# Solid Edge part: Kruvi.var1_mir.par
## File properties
Author: jaanm
Template: Ansi Inch Part.par
Last saved by: jaanm
Revision: 2
Application: Solid Edge
Accuracy: 0,990
Username: jaanm
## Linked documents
Kruvi.var1.par
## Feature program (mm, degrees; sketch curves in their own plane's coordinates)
part copy "CopiedPart_1"
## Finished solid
Body 1: solid body, 36 faces, 97 edges, 64 vertices.
  Faces by surface: plane 23, cylinder 10, spline 2, cone 1
  Edges by curve: line 56, circle 33, intersection 4, spline 4
Bounding box of the edges (mm; curved faces can reach further): 20.000 x 58.500 x 20.000, from (-10, -46.5, -10) to (10, 12, 10).
Cylindrical faces by radius (mm): R3.5 x1, R5 x1, R7 x7, R10 x1
Conical faces (half-angle, radius in mm at the cone's reference point): 45 deg R5 x1
Planar faces by outward normal: +y 8, -y 1, -z 1, oblique 13
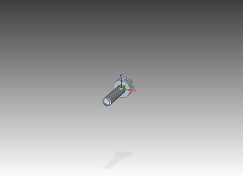
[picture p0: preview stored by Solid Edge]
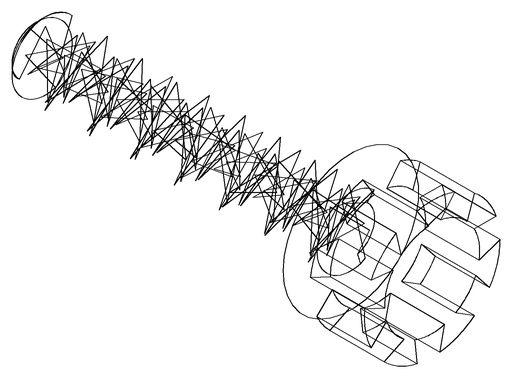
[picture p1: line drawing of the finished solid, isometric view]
